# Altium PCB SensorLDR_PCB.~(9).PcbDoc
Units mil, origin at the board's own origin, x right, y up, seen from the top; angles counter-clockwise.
Board outline 6000 x 4000 mil, 2 copper layers (Top Layer, Bottom Layer); 19 components, 11 nets, 54 pads, 0 vias.
Unrouted connection lines stored in the file: 35.
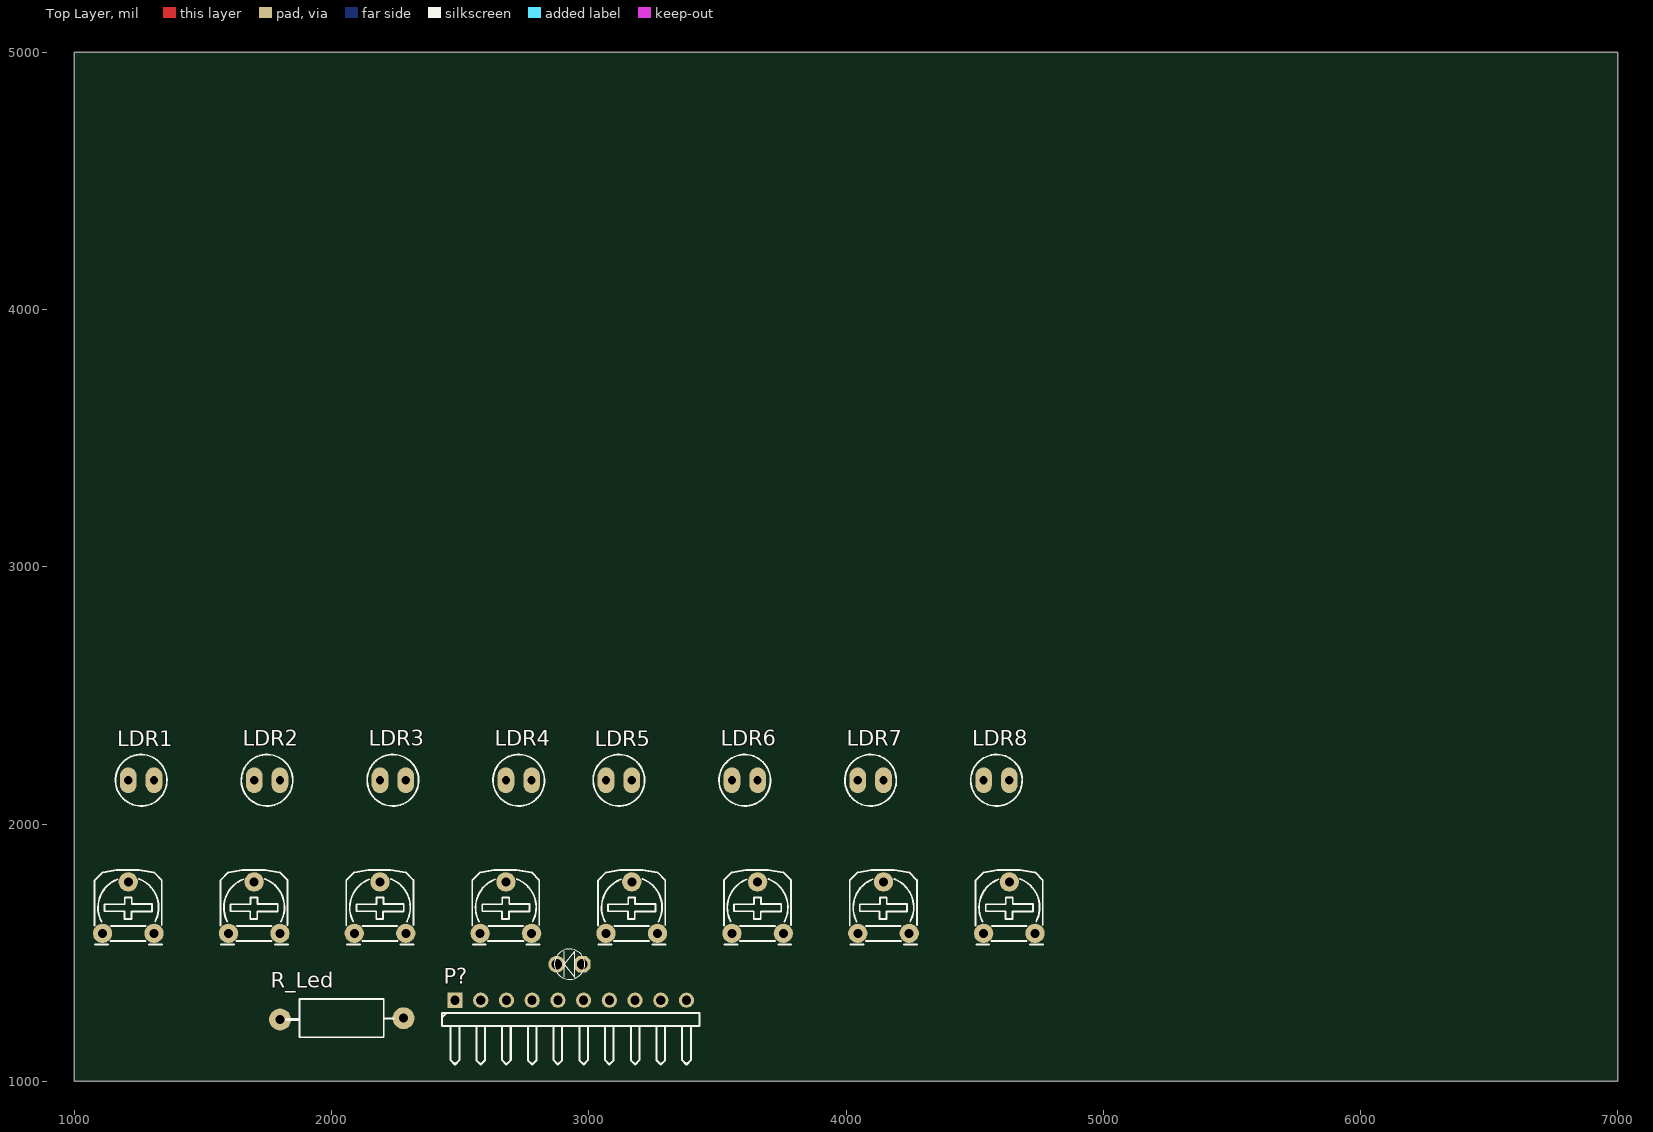
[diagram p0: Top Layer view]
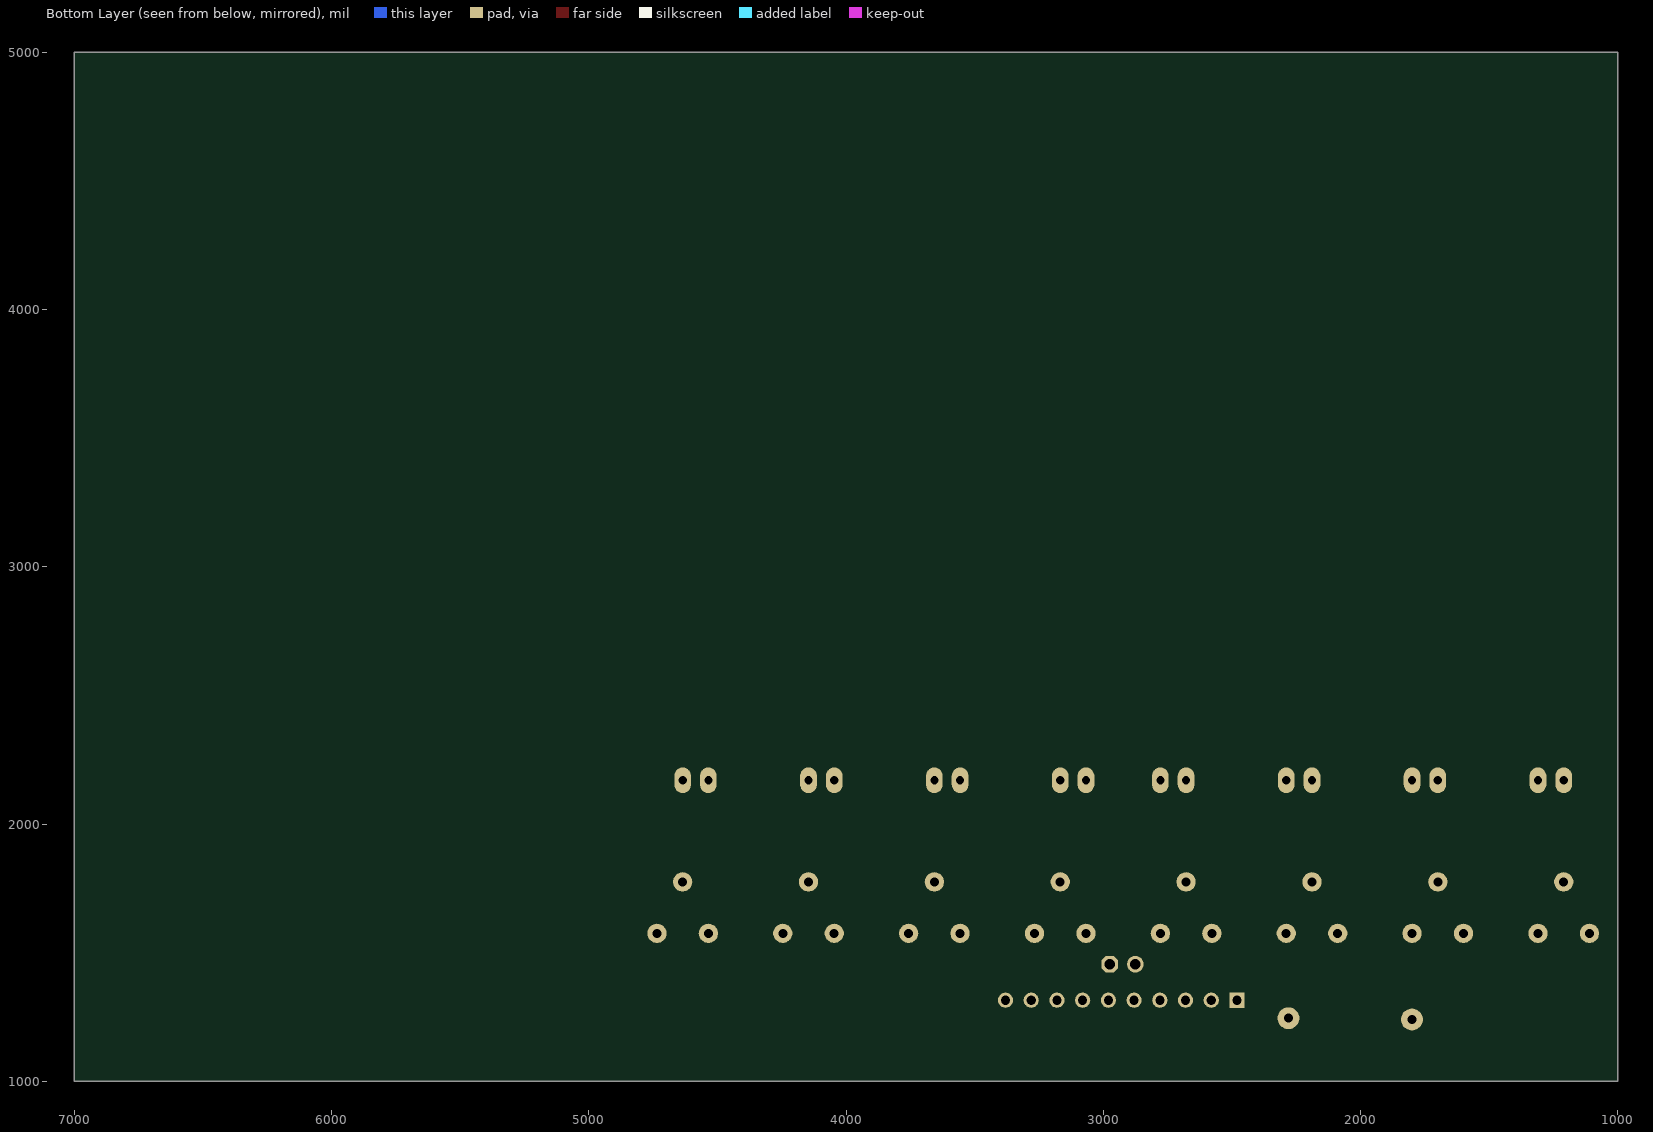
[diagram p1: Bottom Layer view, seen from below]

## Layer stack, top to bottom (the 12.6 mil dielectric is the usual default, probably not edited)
Top Solder: solder mask 0.4, Solder Resist, Dk 3.5
Top Layer: signal copper 1.4
Dielectric 1: dielectric 12.6, FR-4, Dk 4.8
Bottom Layer: signal copper 1.4
Bottom Solder: solder mask 0.4, Solder Resist, Dk 3.5

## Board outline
1000,1000 7000,1000 7000,5000 1000,5000

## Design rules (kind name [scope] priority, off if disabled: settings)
Clearance [All] p1: gap=10 ignorepadtopadclearanceinfootprint=FALSE except(0: Arc-Hole Track-Hole SMDPad-Hole THPad-Hole Via-Hole Fill-Hole Poly-Hole Region-Hole Text-Hole)
PolygonConnect [All] p1: connectstyle=Relief reliefconductorwidth=10 reliefentries=4 polygonreliefangle="90 Angle" airgapwidth=10
RoutingLayers [All] p1: top layer_v5=FALSE bottom layer_v5=TRUE
RoutingVias [All] p1: holewidth=28 width=50 viastyle="Through Hole" minholewidth=28 minwidth=50 maxholewidth=28 maxwidth=50
SolderMaskExpansion [All] p1: expansion=4
Width Others [All] p1: maxlimit=39.37 minlimit=39.37 preferedwidth=39.37
Width VCC [InNet('VCC')] p2: maxlimit=39.37 minlimit=39.37 preferedwidth=39.37
Width GND [InNet('GND')] p3: maxlimit=39.37 minlimit=39.37 preferedwidth=39.37
29 further rules are at their usual default settings.

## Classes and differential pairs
component class SensorLDR: LDR1 LDR2 LDR3 LDR4 LDR5 LDR6 LDR7 LDR8 P? R_Led ""

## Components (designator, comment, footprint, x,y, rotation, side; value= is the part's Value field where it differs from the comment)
LDR1 "LDR" CDS 1310,2170 r180 top
LDR2 "LDR" CDS 1799.29,2170 r180 top
LDR3 "LDR" CDS 2288.57,2170 r180 top
LDR4 "LDR" CDS 2777.86,2170 r180 top
LDR5 "LDR" CDS 3067.14,2170 r0 top
LDR6 "LDR" CDS 3556.43,2170 r0 top
LDR7 "LDR" CDS 4045.71,2170 r0 top
LDR8 "LDR" CDS 4535,2170 r0 top
LED? "LED" LED-3MM-YELLOW 2975,1455 r180 top value="LED 3 ly Single Colour"
P? "Header 10H" HDR1X10H 2480,1315 r0 top
R_Led "Res" RES-1/2W 2020,1245 r0 top
VR1 "50K" VR-S2 1110,1575 r0 top value="Volume 50k"
VR2 "50K" VR-S2 1599.29,1575 r0 top value="Volume 50k"
VR3 "50K" VR-S2 2088.57,1575 r0 top value="Volume 50k"
VR4 "50K" VR-S2 2577.86,1575 r0 top value="Volume 50k"
VR5 "50K" VR-S2 3067.14,1575 r0 top value="Volume 50k"
VR6 "50K" VR-S2 3556.43,1575 r0 top value="Volume 50k"
VR7 "50K" VR-S2 4045.71,1575 r0 top value="Volume 50k"
VR8 "50K" VR-S2 4535,1575 r0 top value="Volume 50k"

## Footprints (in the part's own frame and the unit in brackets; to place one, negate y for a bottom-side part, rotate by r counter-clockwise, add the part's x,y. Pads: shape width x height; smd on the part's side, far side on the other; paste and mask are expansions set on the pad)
CDS [mil] "QUANG TRO"
  oval 65x100 hole 32: 1(0,0) 2(100,0)
  silkscreen extent -50,-100 150,100, body extent -53,-80 153,89, height 138
HDR1X10H [mm] "Connector; Header; 10 Position; Right Angle"
  rect 1.5x1.5 hole 0.9: 1(0,0)
  round 1.5 hole 0.9: 2(2.54,0) 3(5.08,0) 4(7.62,0) 5(10.16,0) 6(12.7,0) 7(15.24,0) 8(17.78,0) 9(20.32,0) 10(22.86,0)
  silkscreen extent -1.27,-6.35 24.13,-1.27
LED-3MM-YELLOW [mil]
  oct 65x65 hole 40: 1(0,0)
  round 65 hole 40: 2(100,0)
  silkscreen extent -9,-59 109,59, body extent -27,-77 117,80, height 181
RES-1/2W [mil]
  round 85 hole 35: 1(-220,-5) 2(260,0)
  silkscreen extent -195,-74 221,75, body extent -230,-60 270,56, height 121
VR-S2 [mil] "Resistor Variable"
  round 75 hole 35: 1(0,0) 2(100,200) 3(200,0)
  silkscreen extent -31,-44 231,246, body extent -87,-30 307,372, height 165

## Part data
LDR1 LDR2 LDR3 LDR4 LDR5 LDR6 LDR7 LDR8: "Quang Tro"
LED?: "LED Single colour Green and Red"
P?: "Header, 10-Pin, Right Angle"
R_Led: Manufacturer="Generic Components"
VR1 VR2 VR3 VR4 VR5 VR6 VR7 VR8: library part VR-S, "Var Resistor"

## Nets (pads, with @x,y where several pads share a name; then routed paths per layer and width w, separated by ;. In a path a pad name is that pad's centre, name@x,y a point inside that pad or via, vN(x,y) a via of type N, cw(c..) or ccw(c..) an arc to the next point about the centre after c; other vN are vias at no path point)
GND: LDR1.1 LDR2.1 LDR3.1 LDR4.1 LDR5.1 LDR6.1 LDR7.1 LDR8.1 P?.2 R_Led.2
NetLED?_2: LED?.2 R_Led.1
S1: LDR1.2 P?.3 VR1.2
S2: LDR2.2 P?.4 VR2.2
S3: LDR3.2 P?.5 VR3.2
S4: LDR4.2 P?.6 VR4.2
S5: LDR5.2 P?.7 VR5.2
S6: LDR6.2 P?.8 VR6.2
S7: LDR7.2 P?.9 VR7.2
S8: LDR8.2 P?.10 VR8.2
VCC: LED?.1 P?.1 VR1.1 VR2.1 VR3.1 VR4.1 VR5.1 VR6.1 VR7.1 VR8.1
pads on no net: VR1.3 VR2.3 VR3.3 VR4.3 VR5.3 VR6.3 VR7.3 VR8.3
